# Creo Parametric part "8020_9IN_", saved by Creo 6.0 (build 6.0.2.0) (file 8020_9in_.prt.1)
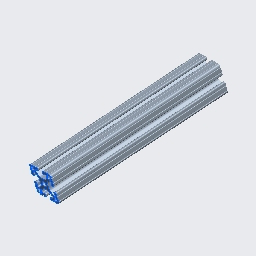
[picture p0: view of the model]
Units: Inch lbm Second (Pro/E Default); INCH, POUND, SECS

Created from: INLBS_PART_SOLID.PRT

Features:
  1. datum plane "RIGHT"
  2. datum plane "TOP"
  3. datum plane "FRONT"
  4. coordinate system
  5. curve "Project 1"
  6. sketch "Sketch 2"
  7. extrusion "Extrude 1"

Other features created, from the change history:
  sketch "Sketch 1"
